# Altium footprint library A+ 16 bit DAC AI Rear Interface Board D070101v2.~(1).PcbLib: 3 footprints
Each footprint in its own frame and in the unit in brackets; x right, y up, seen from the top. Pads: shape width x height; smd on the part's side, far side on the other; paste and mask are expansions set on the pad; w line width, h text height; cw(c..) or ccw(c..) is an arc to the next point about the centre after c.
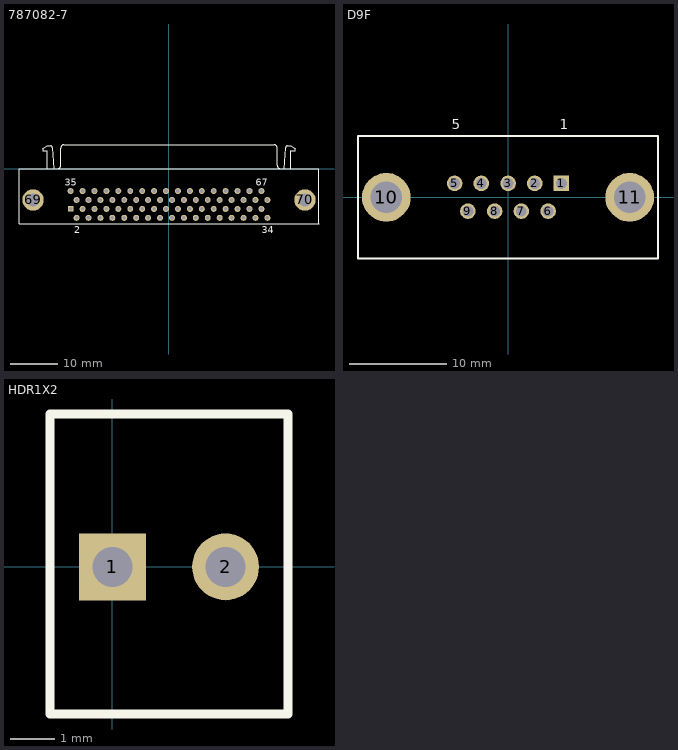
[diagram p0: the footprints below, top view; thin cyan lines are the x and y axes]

## 787082-7 [mm] "Connector; D Subminiature 050 Series; 68 Position; Right Angle"
height 10.44
pads (70):
  rect 1.143x1.143 hole 0.762: 1(-20.955,-8.555)
  round 1.27 hole 0.762: 2(-19.685,-10.46) 3(-18.415,-8.555) 4(-17.145,-10.46) 5(-15.875,-8.555) 6(-14.605,-10.46) 7(-13.335,-8.555) 8(-12.065,-10.46) 9(-10.795,-8.555) 10(-9.525,-10.46) 11(-8.255,-8.555) 12(-6.985,-10.46) 13(-5.715,-8.555) 14(-4.445,-10.46) 15(-3.175,-8.555) 16(-1.905,-10.46) 17(-0.635,-8.555) 18(0.635,-10.46) 19(1.905,-8.555) 20(3.175,-10.46) 21(4.445,-8.555) 22(5.715,-10.46) 23(6.985,-8.555) 24(8.255,-10.46) 25(9.525,-8.555) 26(10.795,-10.46) 27(12.065,-8.555) 28(13.335,-10.46) 29(14.605,-8.555) 30(15.875,-10.46) 31(17.145,-8.555) 32(18.415,-10.46) 33(19.685,-8.555) 34(20.955,-10.46) 35(-20.955,-4.745) 36(-19.685,-6.65) 37(-18.415,-4.745) 38(-17.145,-6.65) 39(-15.875,-4.745) 40(-14.605,-6.65) 41(-13.335,-4.745) 42(-12.065,-6.65) 43(-10.795,-4.745) 44(-9.525,-6.65) 45(-8.255,-4.745) 46(-6.985,-6.65) 47(-5.715,-4.745) 48(-4.445,-6.65) 49(-3.175,-4.745) 50(-1.905,-6.65) 51(-0.635,-4.745) 52(0.635,-6.65) 53(1.905,-4.745) 54(3.175,-6.65) 55(4.445,-4.745) 56(5.715,-6.65) 57(6.985,-4.745) 58(8.255,-6.65) 59(9.525,-4.745) 60(10.795,-6.65) 61(12.065,-4.745) 62(13.335,-6.65) 63(14.605,-4.745) 64(15.875,-6.65) 65(17.145,-4.745) 66(18.415,-6.65) 67(19.685,-4.745) 68(20.955,-6.65)
  round 4.55 hole 2.77: 69(-28.955,-6.65) 70(28.955,-6.65)
Top Overlay:
  lines w0.2: -26.84,4.27 -25.9,4.898 -25.178,4.898 cw(c-25.28,4.5) -24.87,4.5 ; -26.826,4.255 ccw(c-26.6,4.01) -26.85,3.79 -25.97,3.79 -25.97,0 ; -24.87,4.52 -24.5,0 ; -23.76,0.005 ccw(c-23.76,0.7) -23.065,0.7 -23.065,4.4 cw(c-22.37,4.4) -22.37,5.095 ; -22.37,5.11 22.37,5.11 ; 22.37,5.095 cw(c22.37,4.4) 23.065,4.4 23.065,0.7 ccw(c23.76,0.7) 23.76,0.005 ; 24.5,0 24.87,4.52 ; 24.87,4.5 cw(c25.28,4.5) 25.178,4.898 25.9,4.898 26.84,4.27 ; 25.97,0 25.97,3.79 26.85,3.79 ccw(c26.6,4.01) 26.826,4.255 ; -31.95,-11.76 31.95,-11.76 31.95,0 -31.95,0 -31.95,-11.76
  text "2" at -20.185,-13.735 h1.5
  text "34" at 19.705,-13.735 h1.5
  text "67" at 18.435,-3.62 h1.5
  text "35" at -22.205,-3.62 h1.5
3D body: height 0.25, standoff -17.15, extent 0,0 0,0
3D body: height 0.25, standoff -17.15, extent 0.4,-1 0.4,-1
3D body "c-787082-7-y-3d.stp": height 9.49, standoff -3.82, extent -31.941,-11.8 31.941,5.066

## D9F [mm]
height 2.54
pads (11):
  rect 1.6x1.6 hole 1.1: 1(5.486,1.422)
  round 1.6 hole 1.1: 2(2.743,1.422) 3(0.005,1.422) 4(-2.743,1.422) 5(-5.486,1.422) 6(4.115,-1.422) 7(1.372,-1.422) 8(-1.372,-1.422) 9(-4.115,-1.422)
  round 5 hole 3.2: 10(-12.497,0) 11(12.497,0)
Top Overlay:
  lines w0.2: -15.4,-6.3 15.4,-6.3 15.4,6.3 -15.4,6.3 -15.4,-6.3
  text "1" at 5.3,7 h1
  text "5" at -5.8,7 h1
3D body "D9F.stp": height 12.18, standoff -3.16, extent -15.405,-6.299 15.405,6.299

## HDR1X2 [mm] "Connector; Header; 2 Position"
height 6
pads (2):
  rect 1.5x1.5 hole 0.9: 1(0,0)
  round 1.5 hole 0.9: 2(2.54,0)
Top Overlay:
  lines w0.2: -1.397,-3.302 3.937,-3.302 3.937,3.429 -1.397,3.429 -1.397,-3.302
3D body "MOLEX 2pin 3.96mm (022232021).stp": height 10.68, standoff -3.54, extent -1.194,-3.099 3.734,3.251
